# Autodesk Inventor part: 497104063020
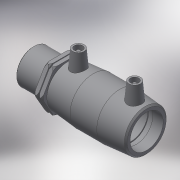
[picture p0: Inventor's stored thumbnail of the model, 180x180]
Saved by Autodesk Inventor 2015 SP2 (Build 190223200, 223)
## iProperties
Created: 2017-06
Part Number: 497104063020
Material: Generic
Description: PLASSON PE MALE TRANSITION COUPLER 63-2"
Document SubType Name: Modeling
Designer: KIM
Mass: 55.0731 g
Surface Area: 148.067 cm^2
Volume: 55.0731 cm^3
Density: 1 g/cm^3
Appearance: Default
Author: KIM
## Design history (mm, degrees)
derived "497104.ipt"
feature "Solid1::497104.ipt"
tag "TaggingFeature1"
body "Solid1"
other parameters: "d0" = 117, "d1" = 63, "d2" = 82, "d3" = 57, "d4" = 39, "d5" = 73.8, "d6" = 59.85, "d7" = 63, "d8" = 168 deg, "d10" = 22.8, "d11" = 7.6, "d29" = 57, "d30" = 14, "d31" = 40.95, "d34" = 5 deg, "d41" = 4, "d42" = 14, "d43" = 0, "d48" = 3, "d49" = 0, "d57" = 48, "d58" = 59.614, "d59" = 47.6912, "d60" = 43.2, "d61" = 83.4596, "d62" = 1.19228, "d65" = 2.46, "d70" = 0.1, "d71" = 48, "d72" = 12, "d73" = 22.8, "d75" = 0, "d76" = 1.2, "d77" = 5.4, "d78" = 83.4596, "d_" = 63, "L_" = 165, "L_2" = 57, "D_1" = 82, "A_" = 57, "d_2" = 12, "L_1" = 48, "D_" = 48, "R_" = 59.614
